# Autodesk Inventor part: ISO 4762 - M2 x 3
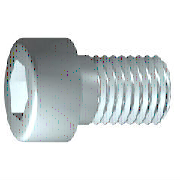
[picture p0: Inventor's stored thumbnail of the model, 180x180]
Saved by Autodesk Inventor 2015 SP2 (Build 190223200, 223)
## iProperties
Created: 2012-02
Part Number: ISO 4762 - M2 x 3
Material: Edelstahl, 440C
Description: Innensechskantschraube
Document SubType Name: Modeling
Standard: ISO 4762
Designer: rYan
Standard Revision: 1998
Standards Organization: DIN
Language: de-DE
Size Designation: M2 x 3
Categories: <MemberInstance><Categories><Category DisplayName="Verbindungselemente" InternalName="e4da775c-781d-43d5-af7c-5136215cf5a6" Mnemonic="FSTN"><Category DisplayNam
Density: 7.75 g/cm^3
Appearance: Halbpoliert
IsCustomPart: 0
Author: rYan
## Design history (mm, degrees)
sketch "Skizze1"
  geometry: L1 (-0.5, 0)-(3, 0); L2 (3, 0)-(3, 1); L3 (3, 1)-(1, 1); L4 (1, 1)-(0.755, 1); L5 (0.755, 1)-(0, 1); L6 (0, 1)-(0, 1.9); L7 (0, 1.9)-(-2, 1.9); L8 (-2, 1.9)-(-2, 0.866); L9 (-2, 0.866)-(-1, 0.866); L10 (-1, 0.866)-(-0.5, 0); L11 (-3, 0)-(4, 0) reference; L12 (0, -0.38)-(0, 2.28) reference; L13 (1, 1)-(0, 1)
  constraints: 22 end point, 6 parallel, 2 collinear, 2 perpendicular, 1 horizontal, 1 point on line
  dimensions: "d1" = 2 distance from line of L3.end L2 (= GEL); "d2" = 0.24548 distance of L4.end L3.end (computed from GAL); "d3" = 2 distance between parallel lines of L8 L6 (= KOH); "d4" = 1 distance of L8.end L9.end (= INTI); "d5" = 60 deg angle of L10 L1; "d6" = 2 diameter of L3 L1 (= GD); "d7" = 2 diameter of L5 L1 (= BDM); "d8" = 1.73205 diameter of L9 L1 (= 1.1547 x SW); "d9" = 3.8 diameter of L7 L1 (= KOD); "d26" = 3 distance between parallel lines of L12 L2 (= NLG)
revolve "Körper" sketch "Skizze1" stored, may be unused: angle "d10" = 90 deg
sketch "Skizze2"
  geometry: L1 (0, -2.66)-(0, 2.66) reference; L2 (-2.66, 0)-(2.66, 0) reference; L3 (0.866, 0)-(0.433, -0.75); L4 (0.433, -0.75)-(-0.433, -0.75); L5 (-0.433, -0.75)-(-0.866, 0); L6 (-0.866, 0)-(-0.433, 0.75); L7 (-0.433, 0.75)-(0.433, 0.75); L8 (0.433, 0.75)-(0.866, 0); 2 further points
  constraints: 12 end point, 1 coincident, 1 horizontal alignment, 1 point on line, 12 other
extrude "Loch" join sketch "Skizze2" stored distance "d11" = 10; taper "d12" = 0 deg
workplane "Work Plane1"
fillet "Fillet2" dims "d30" = 0.1 (= R)
body "Solid1"
fillet "Rundung1" dims "d17" = 0.2 (= RR)
feature "Gewinde" dims "d13" = 2 (= GEL), "d14" = 0
chamfer "Fase1" distance "d15" = 0.24538 (= -0.5 x SPD + 0.5 x GD); stored, may be unused: second distance "d16" = 0.24538 (= GUL), angle "d27" = 45 deg
other parameters: "GD" = 2 [user parameter; used in 2 equation terms], "NLG" = 3 [user parameter; used in 1 equation term], "GEL" = 2 [user parameter; used in 2 equation terms], "KOD" = 3.8 [user parameter; used in 1 equation term], "KOH" = 2 [user parameter; used in 1 equation term], "INTI" = 1 [user parameter; used in 1 equation term], "GAL" = 0.24538 (= 0.61345 x PTC) [user parameter; used in 1 equation term], "GUL" = 0.24538 (= 0.61345 x PTC) [user parameter; used in 1 equation term], "BDM" = 2 (= NND) [user parameter; used in 1 equation term], "SW" = 1.5 [user parameter; used in 2 equation terms], "RR" = 0.2 [user parameter; used in 1 equation term], "SPD" = 1.50924 (= NND - 1.2269 x PTC) [user parameter; used in 1 equation term], "d19" = 0, "d28" = 0, "d29" = 0, "R" = 0.1 [user parameter; used in 1 equation term], "TOA" = 30 deg [user parameter], "GD1" = 1.50924 (= THREADDIA - 1.2269 x PTC) [user parameter], "THREADDIA" = 2 [user parameter; used in 1 equation term], "FAWI" = 45 deg [user parameter], "TPU" = 25 (computed from PTC) [user parameter], "PTC" = 0.4 [user parameter; used in 5 equation terms], "NND" = 2 [user parameter; used in 2 equation terms], "E0" = 1.7325 (= 1.155 x SW) [user parameter]
